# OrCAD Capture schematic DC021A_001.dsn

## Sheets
1 Page 3 - Hardware: size B; title: ADC1173EVM (Hardware); rev: A; note: DC021-001
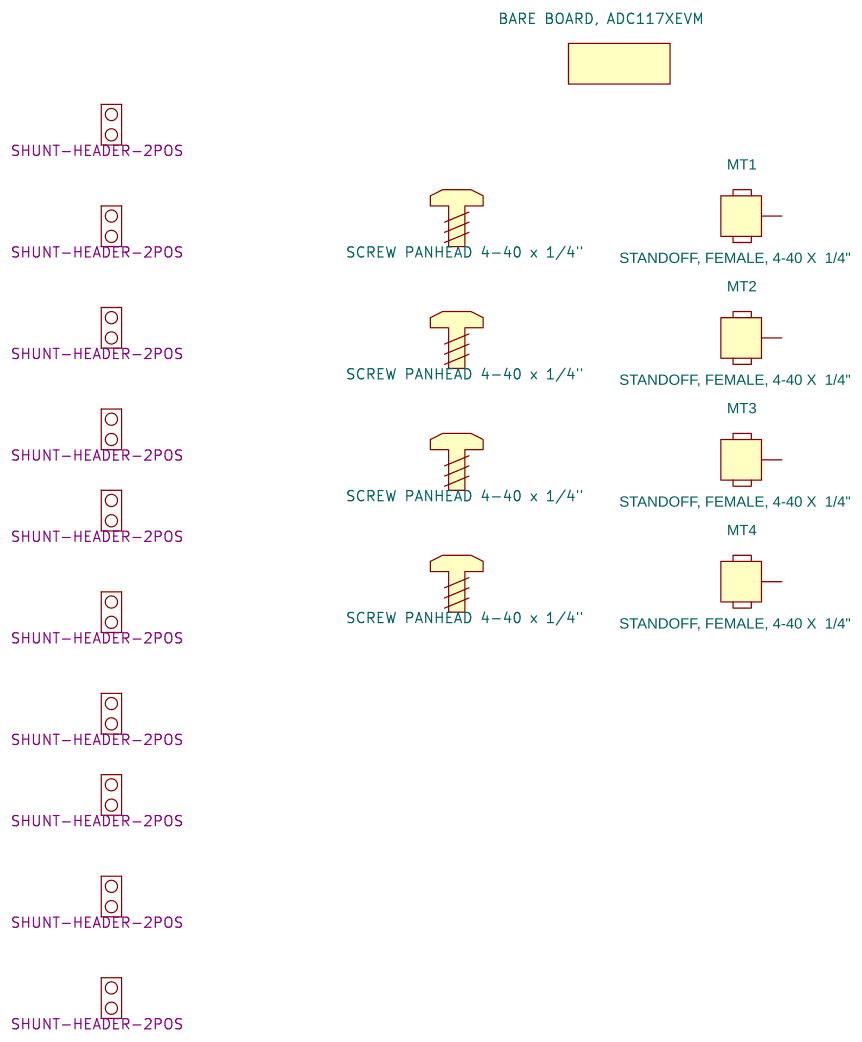
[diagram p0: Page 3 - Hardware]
2 Page 2 - Power: size B; title: ADC1173EVM (Power)
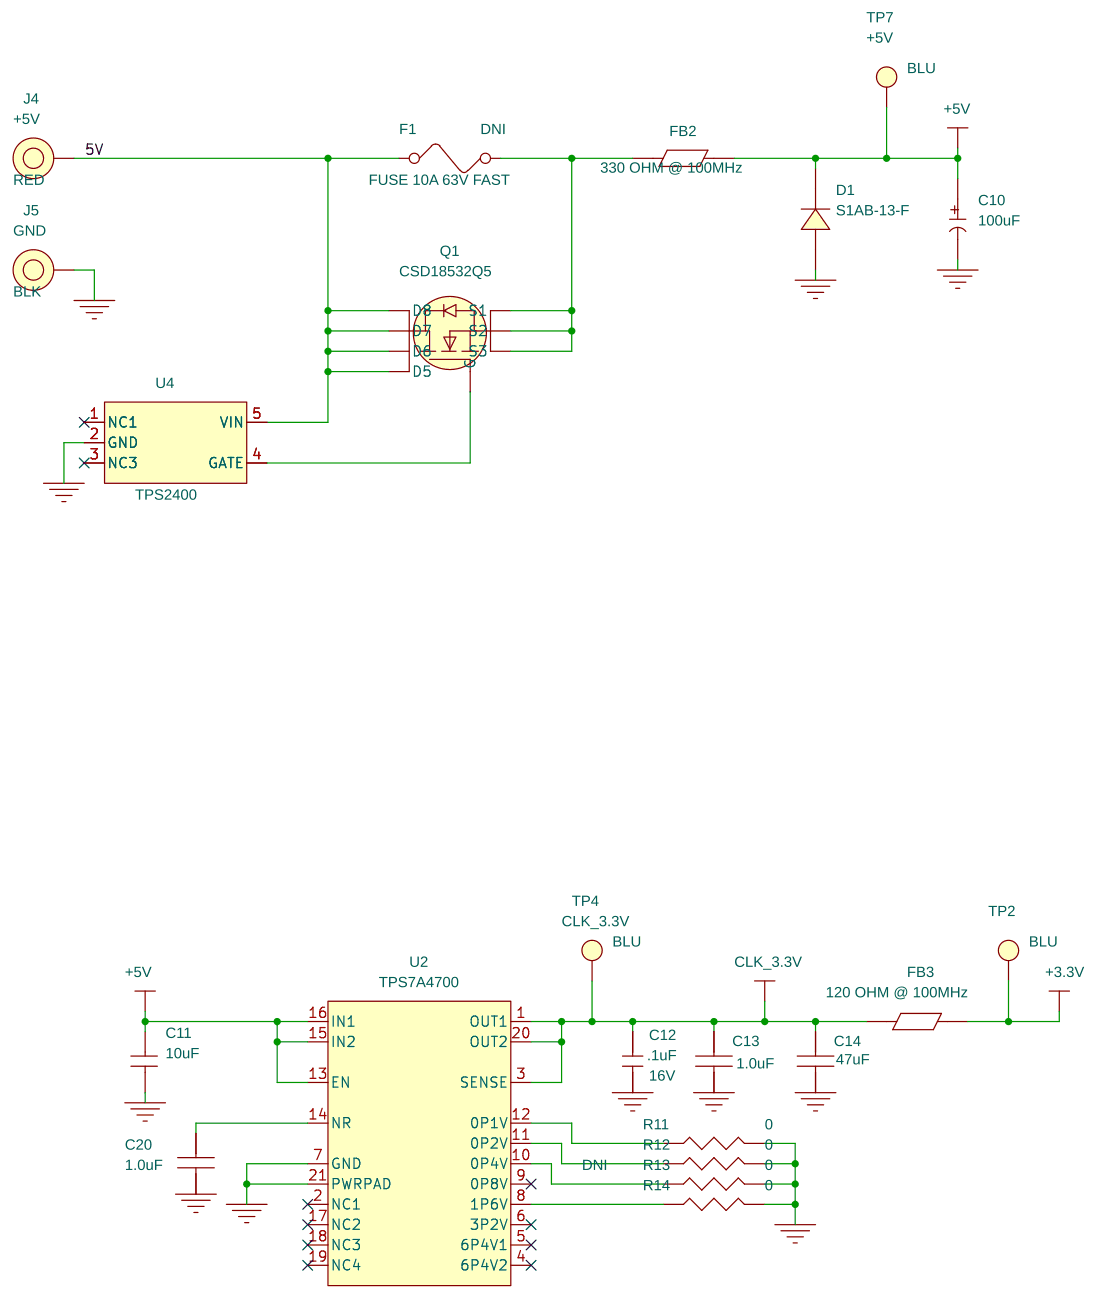
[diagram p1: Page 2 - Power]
3 Page 1 - Inputs: size B; title: ADC1173EVM
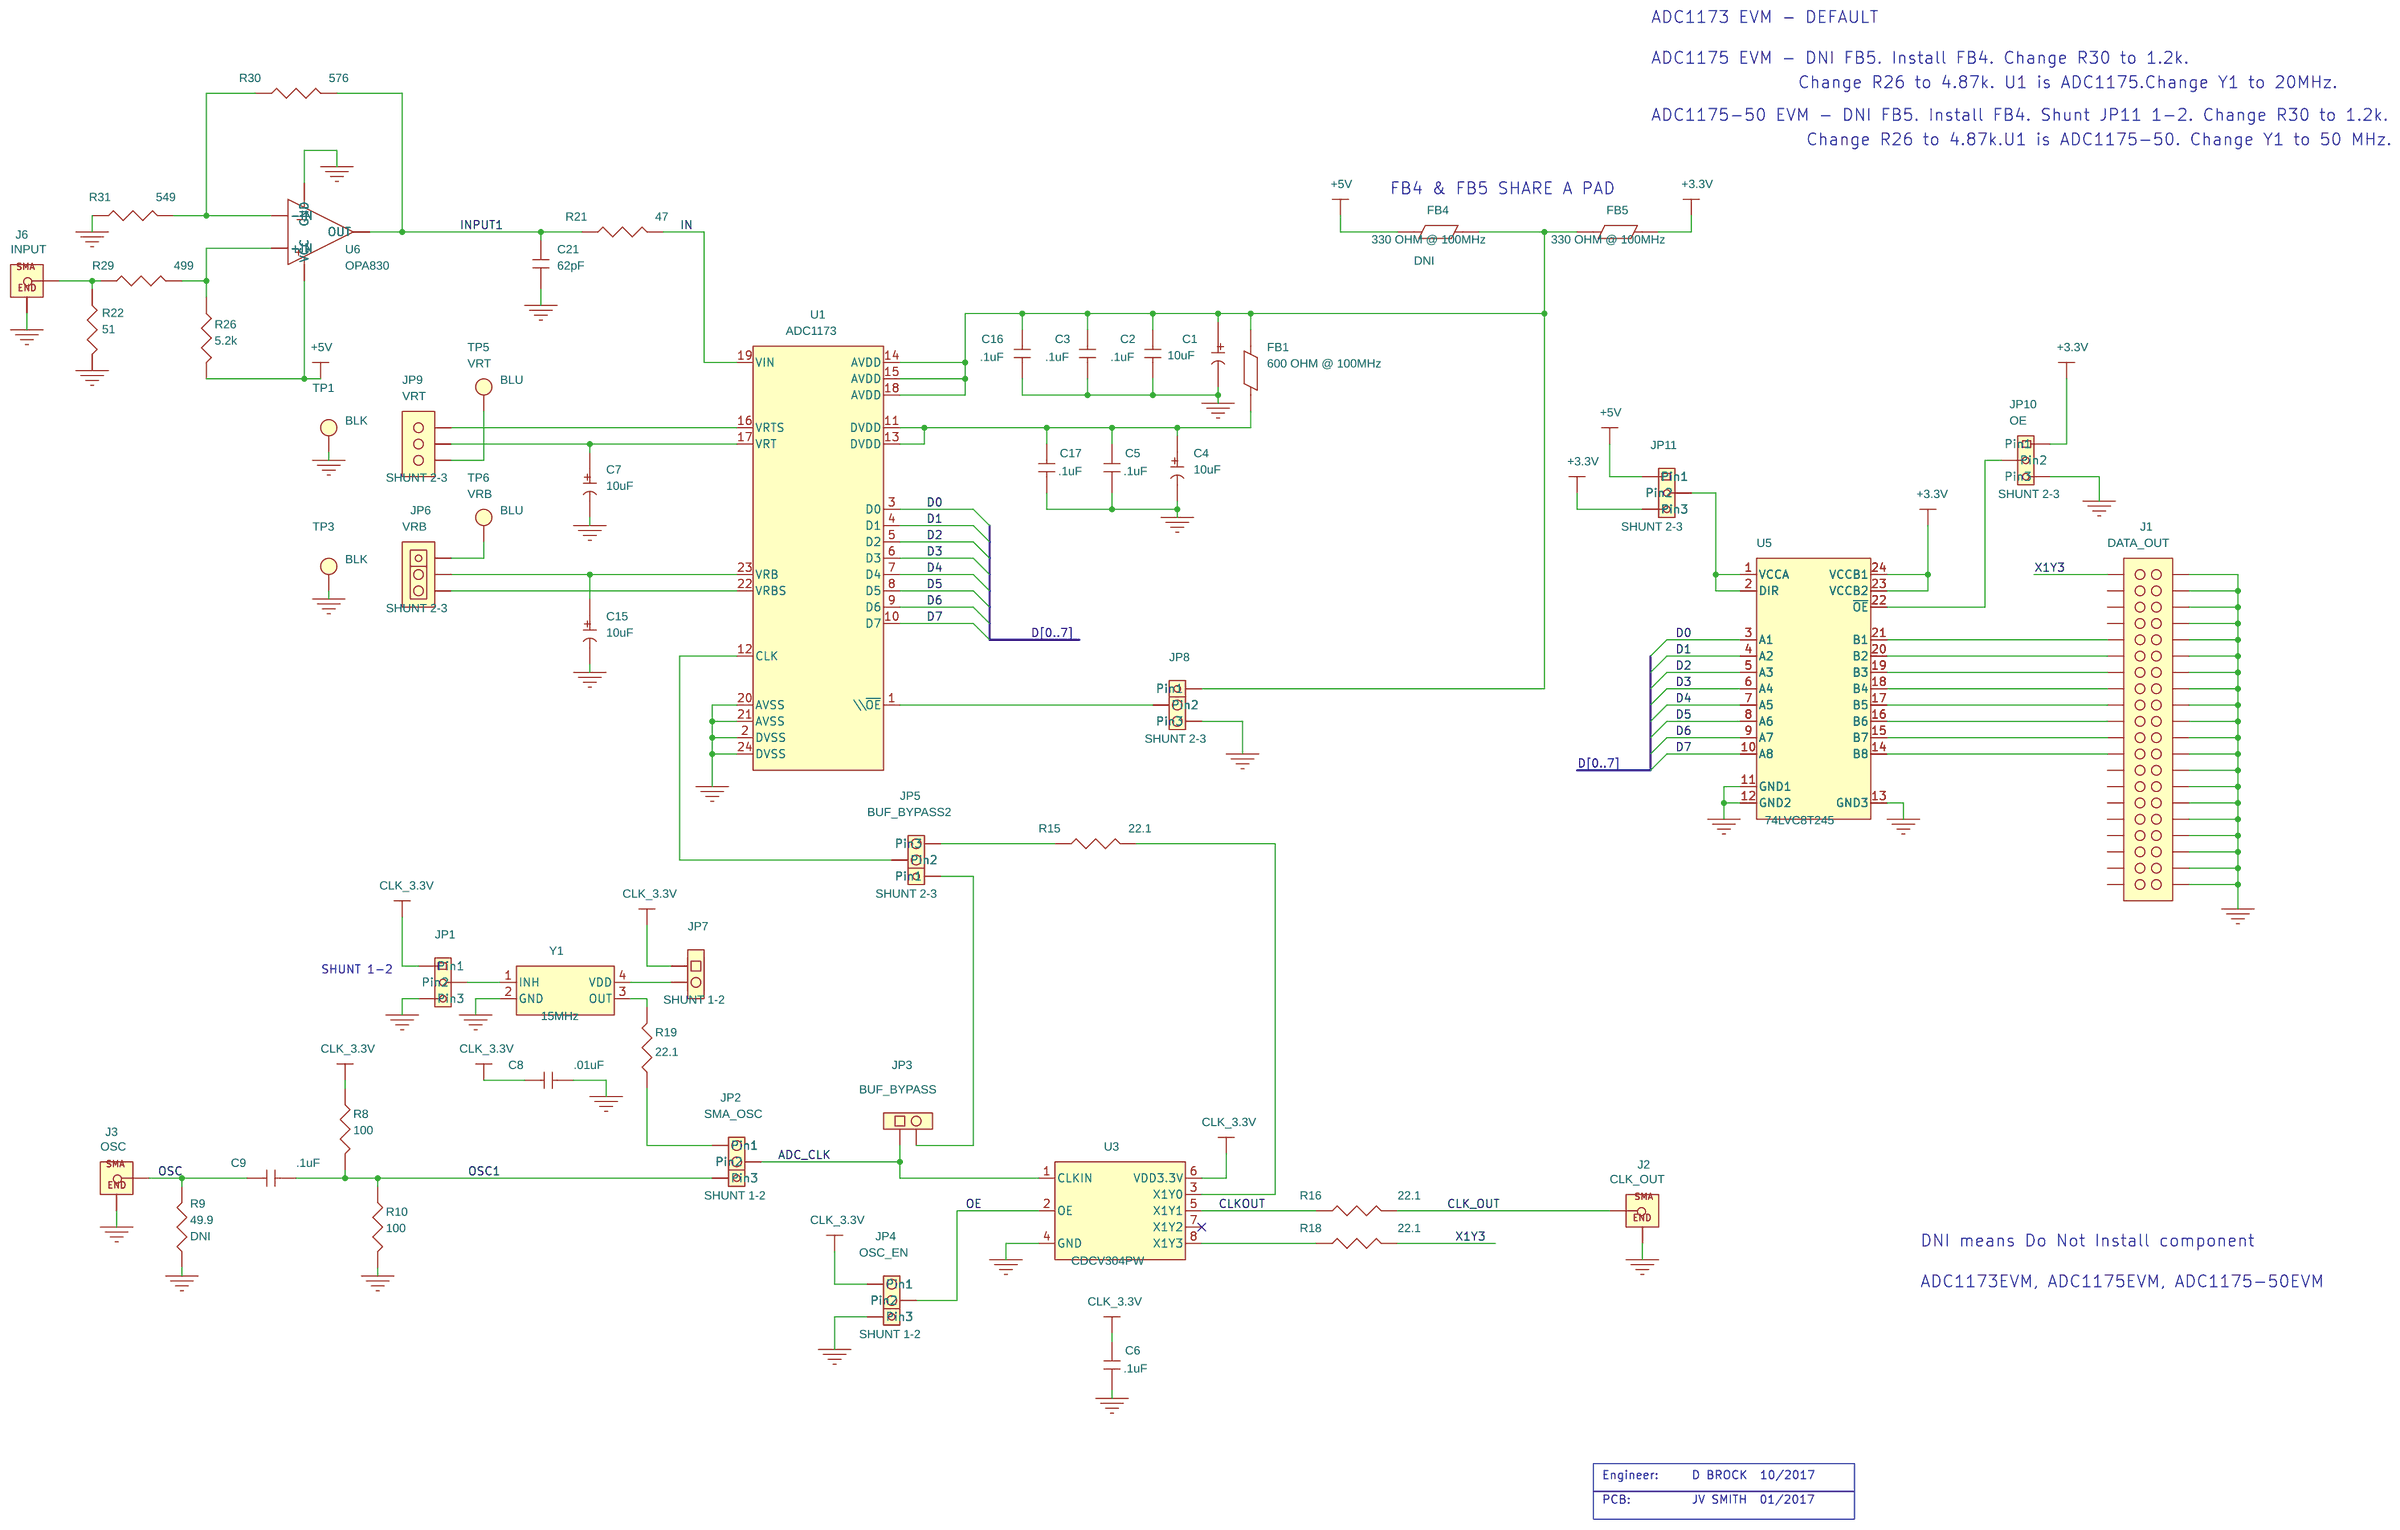
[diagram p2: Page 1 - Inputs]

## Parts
sheet Page 1 - Inputs
C1  10uF  [TANT_A]
C2  .1uF  [0402]
C3  .1uF  [0402]
C4  10uF  [TANT_A]
C5  .1uF  [0402]
C6  .1uF  [0402]
C7  10uF  [TANT_A]
C8  .01uF  [0402]
C9  .1uF  [0402]
C15  10uF  [TANT_A]
C16  .1uF  [0402]
C17  .1uF  [0402]
C21  62pF  [0402]
FB1  600 OHM @ 100MHz  [IND_0603]
FB4  330 OHM @ 100MHz  [IND_0603]
FB5  330 OHM @ 100MHz  [IND_0603]
J1  HDR, THVT, 40POS, .100  [HDR_THVT_2x20_100_M]
J2  SMA, THVT,  50OHMS  [SMA_THVT_312X312]
J3  SMA, THVT,  50OHMS  [SMA_THVT_312X312]
J6  SMA, THVT,  50OHMS  [SMA_THVT_312X312]
JP1  HEADER, 3POS, .100  [HDR_THVT_1x3_100_M]
JP2  HEADER, 3POS, .100  [HDR_THVT_1x3_100_M]
JP3  JUMPER_1X2_100  [HDR_THVT_1X2_100_M]
JP4  HEADER, 3POS, .100  [HDR_THVT_1x3_100_M]
JP5  HEADER, 3POS, .100  [HDR_THVT_1x3_100_M]
JP6  HEADER, 3POS, .100  [HDR_THVT_1x3_100_M]
JP7  HDR, 2POS, .100  [HDR_THVT_1X2_100_M]
JP8  HEADER, 3POS, .100  [HDR_THVT_1x3_100_M]
JP9  HEADER, 3POS, .100  [HDR_THVT_1x3_100_M]
JP10  JUMPER_1X3_100  [HDR_THVT_1x3_100_M]
JP11  HEADER, 3POS, .100  [HDR_THVT_1x3_100_M]
R8  100  [0402]
R9  49.9  [0402]
R10  100  [0402]
R15  22.1  [0402]
R16  22.1  [0402]
R18  22.1  [0402]
R19  22.1  [0402]
R21  47  [0402]
R22  51  [0402]
R26  5.2k  [0402]
R29  499  [0402]
R30  576  [0402]
R31  549  [0402]
TP1  BLK  [TP_THVT_100_RND_GND]
TP3  BLK  [TP_THVT_100_RND_GND]
TP5  BLU  [TP_THVT_100_RND]
TP6  BLU  [TP_THVT_100_RND]
U1  ADC1173  [TSSOP_24_311x177_26]
U3  CDCV304PW  [TSSOP_8_177x122_26]
U5  74LVC8T245  [SOIC_24_610x299_50]
U6  OPA830  [SOP_5_118x67_37]
Y1  15MHz  [XTAL_4_SM_85x104]
Z_SH-H1  SHUNT-HEADER
Z_SH-H2  SHUNT-HEADER
Z_SH-H4  SHUNT-HEADER
Z_SH-H5  SHUNT-HEADER
Z_SH-H6  SHUNT-HEADER
Z_SH-H7  SHUNT-HEADER
Z_SH-H8  SHUNT-HEADER
Z_SH-J1  SHUNT-HEADER
sheet Page 2 - Power
C10  100uF  [TANT_D]
C11  10uF  [0805]
C12  .1uF  [0402]
C13  1.0uF  [0603]
C14  47uF  [1206]
C20  1.0uF  [0603]
D1  S1AB-13-F  [DIODE_S1AB_SMB]
F1  FUSE 10A 63V FAST  [1206]
FB2  330 OHM @ 100MHz  [IND_0603]
FB3  120 OHM @ 100MHz  [1206]
J4  RED  [JACK_THVT_BANANA_315DRILL]
J5  BLK  [JACK_THVT_BANANA_315DRILL]
Q1  CSD18532Q5  [SON_Q5B_8]
R11  0  [0402]
R12  0  [0402]
R13  0  [0402]
R14  0  [0402]
TP2  BLU  [TP_THVT_100_RND]
TP4  BLU  [TP_THVT_100_RND]
TP7  BLU  [TP_THVT_100_RND]
U2  TPS7A4700  [qfn20_rgw_p65pitch]
U4  TPS2400  [DBV5]
sheet Page 3 - Hardware
MT1  STANDOFF, FEMALE, 4-40 X  1/4"  [MFG125_PLATED]
MT2  STANDOFF, FEMALE, 4-40 X  1/4"  [MFG125_PLATED]
MT3  STANDOFF, FEMALE, 4-40 X  1/4"  [MFG125_PLATED]
MT4  STANDOFF, FEMALE, 4-40 X  1/4"  [MFG125_PLATED]
Z_BOARD2  BARE BOARD, ADC117XEVM
Z_SCREW2  SCREW PANHEAD 4-40 x 1/4"
Z_SCREW3  SCREW PANHEAD 4-40 x 1/4"
Z_SCREW4  SCREW PANHEAD 4-40 x 1/4"
Z_SCREW5  SCREW PANHEAD 4-40 x 1/4"
Z_SH-J2  SHUNT- HEADER
Z_SH-J3  SHUNT- HEADER
Z_SH-J4  SHUNT- HEADER
Z_SH-J5  SHUNT- HEADER
Z_SH-J6  SHUNT- HEADER
Z_SH-J7  SHUNT- HEADER
Z_SH-J8  SHUNT- HEADER
Z_SH-J9  SHUNT- HEADER
Z_SH-J10  SHUNT- HEADER
Z_SH-J11  SHUNT- HEADER

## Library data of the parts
C1 C4 C7 C15 = CAP_TANT_A_0: Mfr_Part_Number: T491A106K010AT
C2 C3 C5 C6 C9 C16 C17 = CAP_0402_0.1uF
C8 = CAP_0402_0.01uF
C21 = CAP_0402_68pF: Mfr_Name: SAMSUNG; Mfr_Part_Number: CL05C620JB5NNNC
FB1 = FERRITE_BEAD_0603_600_H: Mfr_Part_Number: BLM18AG601SN1D
FB4 = FERRITE_BEAD_0603_600_H: Mfr_Part_Number: BLM18PG331SN1D_DNI; Note: DNI
FB5 = FERRITE_BEAD_0603_600_H: Mfr_Part_Number: BLM18PG331SN1D
J1 = HEADER_2x20_100: Mfr_Part_Number: TSW-120-07-G-D; TI_SILKTEXT: DATA_OUT
J2 = TMP_102603: Mfr_Part_Number: 142-0701-201; TI_Silktext: CLK_OUT
J3 = TMP_102603: Mfr_Part_Number: 142-0701-201; TI_Silktext: OSC
J6 = TMP_102603: Mfr_Part_Number: 142-0701-201; TI_Silktext: INPUT
JP1 = JUMPER_1X3_100
JP2 = JUMPER_1X3_100: Note: SHUNT 1-2; TI_Silktext: SMA_OSC
JP3 = JUMPER_1X2_100: SILK: BUF_BYPASS
JP4 = JUMPER_1X3_100: Note: SHUNT 1-2; TI_Silktext: OSC_EN
JP5 = JUMPER_1X3_100: Note: SHUNT 2-3; TI_Silktext: BUF_BYPASS2
JP6 = HEADER_1x3_100: Note: SHUNT 2-3; TI_SILKTEXT: VRB
JP7 = JUMPER_1X2_100: Note: SHUNT 1-2; SILK: SILK
JP8 JP11 = JUMPER_1X3_100: Note: SHUNT 2-3; TI_Silktext: ADC_OE
JP9 = HEADER_1x3_100: Note: SHUNT 2-3; TI_SILKTEXT: VRT
JP10 = JUMPER_1X3_100: Note: SHUNT 2-3; TI_Silktext: OE
R8 R10 = Res_0402_100
R9 = Res_0402_49.9_H: Mfr_Part_Number: ERJ-2RKF49R9X_DNI; Note: DNI
R15 R16 R18 R19 = Res_0402_22.1_H
R21 = Res_0402_47
R22 = Res_0402_51_.5%: Mfr_Part_Number: ERA-2AED510X; TOL: .1%
R26 = Res_0805_21.5k: Mfr_Part_Number: ERJ-2RKF5231X
R29 = Res_0402_499_H
R30 = Res_0402_1.2k: Mfr_Part_Number: ERJ-2RKF5760X
R31 = Res_0402_560_H: Mfr_Part_Number: ERJ-2RKF5490X
TP1 TP3 = TESTPOINT_BLK
TP5 = TESTPOINT_BLUE: TI_SILKTEXT: VRT
TP6 = TESTPOINT_BLUE: TI_SILKTEXT: VRB
U1 = ADC1175: Mfr_Part_Number: ADC1173CIMTCX/NOPB
U3 = CDCV304PW
U5 = SN74LVC8T245
U6 = OPA376DCK: Mfr_Part_Number: OPA830IDBVT
Y1 = OSC_4_SM_KYOCERA_40MHz: Mfr_Name: EPSON; Mfr_Part_Number: SG-210STF 15.000000MHz
Z_SH-H1 Z_SH-H2 Z_SH-H4-Z_SH-H8 = SHUNT-HEADER_-_3POS
Z_SH-J1 = SHUNT-HEADER_-_2POS
C10 = CAP_TANT_D_0: Mfr_Name: Panasonic; Mfr_Part_Number: 20TQC100MYF
C11 = CAP_NP_1: Mfr_Name: MURATA; Mfr_Part_Number: GRM21BR61E106KA73L; TOL: 10%; VOLTAGE: 25V
C12 = CAP0603: Mfr_Name: MURATA; Mfr_Part_Number: GRM155R71C104KA88D; TOL: 10%; Voltage: 16V
C13 C20 = CAP_NP_0: Mfr_Name: TDK CORP; Mfr_Part_Number: C1608X7R1C105K080AC; TOL: 10%; VOLTAGE: 16V
C14 = CAP_NP_0: Mfr_Name: MURATA; Mfr_Part_Number: GRM31CR61A476ME15L; TOL: 20%; VOLTAGE: 10V
D1 = DIODE_S1BB
F1 = FUSE_0: Mfr_Name: TE Connectivity; Mfr_Part_Number: 1206SFF200F/63-2_DNI; Note: DNI
FB2 = FERRITE_BEAD_0603_600_H: Mfr_Part_Number: LM18PG331SN1D
FB3 = FERRITE_BEAD_1206_120_H: Mfr_Part_Number: BLM31PG121SN1L
J4 = BANANA_JACK_RED_RoHS: Mfr_Name: TENMA; Mfr_Part_Number: SPC15363; TI_Silktext: +5V
J5 = BANANA_JACK_BLK_RoHS: Mfr_Name: TENMA; Mfr_Part_Number: SPC15354; TI_Silktext: GND
Q1 = CSD18532Q5B: Mfr_Name: Texas Instruments
R11-R13 = R: Mfr_Name: PANASONIC; Mfr_Part_Number: ERJ-2GE0R00X_DNI; Note: DNI; TOL: 5%
R14 = R: Mfr_Name: PANASONIC; Mfr_Part_Number: ERJ-2GE0R00X; TOL: 5%
TP2 = TESTPOINT_BLUE: TI_SILKTEXT: +3V
TP4 = TESTPOINT_BLUE: TI_SILKTEXT: CLK_3.3V
TP7 = TESTPOINT_BLUE: TI_SILKTEXT: +5V
U2 = TPS7A4700: Mfr_Name: Texas Instruments; Mfr_Part_Number: TPS7A4700RGWT
U4 = TPS2400: Mfr_Name: Texas Instruments; Mfr_Part_Number: TPS2400DBVT
MT1-MT4 = MOUNTING_HOLE_1_3_16: Mfr_Name: KEYSTONE; Mfr_Part_Number: 1891
Z_BOARD2 = BARE_BOARD: Mfr_Name: TTM; Mfr_Part_Number: ADC1173EVM REV A
Z_SCREW2-Z_SCREW5 = STANDOFF-SCREW_3_4: Mfr_Part_Number: PMSSS 440 0025 PH
Z_SH-J2-Z_SH-J11 = SHUNT-HEADER_-_2POS: ID: SHUNT-HEADER-2POS; Note: SHUNT-HEADER-2POS

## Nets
5V: F1.1 J4.1 Q1.5(D5) Q1.6(D6) Q1.7(D7) Q1.8(D8) U4.5(VIN)
+3.3V: FB3.2 FB5.2 JP10.1(Pin1) JP11.3(Pin3) TP2.1(TP) U5.23(VCCB2) U5.24(VCCB1)
+5V: C10.1 C11.1 D1.2(CATHODE) FB2.2 FB4.1 JP11.1(Pin1) R26.2 TP7.1(TP) U2.13(EN) U2.15(IN2) U2.16(IN1) U6.5(VCC)
GND: C1.2 C2.2 C3.2 C4.2 C5.2 C6.2 C7.2 C8.2 C10.2 C11.2 C12.2 C13.2 C14.2 C15.2 C16.2 C17.2 C20.2 C21.2 D1.1(ANODE) J1.2 J1.4 J1.6 J1.8 J1.10 J1.12 J1.14 J1.16 J1.18 J1.20 J1.22 J1.24 J1.26 J1.28 J1.30 J1.32 J1.34 J1.36 J1.38 J1.40 J2.2(GND) J2.3(GND) J2.4(GND) J2.5(GND) J3.2(GND) J3.3(GND) J3.4(GND) J3.5(GND) J5.1 J6.2(GND) J6.3(GND) J6.4(GND) J6.5(GND) JP1.3(Pin3) JP4.3(Pin3) JP8.3(Pin3) JP10.3(Pin3) R9.1 R10.2 R11.1 R12.1 R13.1 R14.1 R22.2 R31.1 TP1.1(TP) TP3.1(TP) U1.2(DVSS) U1.20(AVSS) U1.21(AVSS) U1.24(DVSS) U2.7(GND) U2.21(PWRPAD) U3.4(GND) U4.2(GND) U5.11(GND1) U5.12(GND2) U5.13(GND3) U6.2(GND) Y1.2(GND)
ADC_CLK: JP2.2(Pin2) JP3.1 U3.1(CLKIN)
CLK_3.3V: C6.1 C8.1 C12.1 C13.1 C14.1 FB3.1 JP1.1(Pin1) JP4.1(Pin1) JP7.1 R8.1 TP4.1(TP) U2.1(OUT1) U2.3(SENSE) U2.20(OUT2) U3.6(VDD3.3V)
CLK_OUT: J2.1(CENTER) R16.2
CLKOUT: R16.1 U3.5(X1Y1)
D0: U1.3(D0) U5.3(A1)
D1: U1.4(D1) U5.4(A2)
D2: U1.5(D2) U5.5(A3)
D3: U1.6(D3) U5.6(A4)
D4: U1.7(D4) U5.7(A5)
D5: U1.8(D5) U5.8(A6)
D6: U1.9(D6) U5.9(A7)
D7: U1.10(D7) U5.10(A8)
IN: R21.1 U1.19(VIN)
INPUT1: C21.1 R21.2 R30.2 U6.4(OUT)
OE: JP4.2(Pin2) U3.2(OE)
OSC: C9.1 J3.1(CENTER) R9.2
OSC1: C9.2 JP2.3(Pin3) R8.2 R10.1
X1Y3: J1.1 R18.2
N19769118: R19.2 Y1.3(OUT)
N19769226: JP2.1(Pin1) R19.1
N19799665: R15.2 U3.3(X1Y0)
N19799687: R18.1 U3.8(X1Y3)
N19818955: J1.23 U5.14(B8)
N19818957: J1.21 U5.15(B7)
N19818959: J1.19 U5.16(B6)
N19818961: J1.17 U5.17(B5)
N19819026: J1.9 U5.21(B1)
N19819028: J1.11 U5.20(B2)
N19819030: J1.13 U5.19(B3)
N19819032: J1.15 U5.18(B4)
N19819185: JP3.2 JP5.1(Pin1)
N19819194: JP5.2(Pin2) U1.12(CLK)
N19819218: JP5.3(Pin3) R15.1
N19821064: JP1.2(Pin2) Y1.1(INH)
N19821339: JP7.2 Y1.4(VDD)
N19861116: C1.1 C2.1 C3.1 C16.1 FB1.2 FB4.2 FB5.1 JP8.1(Pin1) U1.14(AVDD) U1.15(AVDD) U1.18(AVDD)
N19861142: C4.1 C5.1 C17.1 FB1.1 U1.11(DVDD) U1.13(DVDD)
N19864072: J6.1(CENTER) R22.1 R29.1
N19864545: JP8.2(Pin2) U1.1(\\~{OE})
N19865533: JP9.3 U1.16(VRTS)
N19865546: C7.1 JP9.2 U1.17(VRT)
N19865555: JP9.1 TP5.1(TP)
N19865562: C15.1 JP6.2 U1.23(VRB)
N19865571: JP6.3 U1.22(VRBS)
N19865580: JP6.1 TP6.1(TP)
N19873407: C20.1 U2.14(NR)
N19873435: R14.2 U2.8(1P6V)
N19873437: R12.2 U2.11(0P2V)
N19873439: R11.2 U2.12(0P1V)
N19873449: R13.2 U2.10(0P4V)
N19874252: F1.2 FB2.1 Q1.1(S1) Q1.2(S2) Q1.3(S3)
N19874302: Q1.4(G) U4.4(GATE)
N19886844: JP10.2(Pin2) U5.22(~{OE})
N19887644: JP11.2(Pin2) U5.1(VCCA) U5.2(DIR)
N19892118: R26.1 R29.2 U6.1(+IN)
N19894018: R30.1 R31.2 U6.3(-IN)

Not connected (* = marked no-connect by the designer): J1 3 5 7 25 27 29 31 33 35 37 39; MT1 1; MT2 1; MT3 1; MT4 1; U2 2(NC1)* 4(6P4V2)* 5(6P4V1)* 6(3P2V)* 9(0P8V)* 17(NC2)* 18(NC3)* 19(NC4)*; U3 7(X1Y2)*; U4 1(NC1)* 3(NC3)*

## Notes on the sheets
sheet 3
- ADC1173 EVM - DEFAULT
- ADC1175 EVM - DNI FB5. Install FB4. Change R30 to 1.2k.
- Change R26 to 4.87k. U1 is ADC1175.Change Y1 to 20MHz.
- ADC1175-50 EVM - DNI FB5. Install FB4. Shunt JP11 1-2. Change R30 to 1.2k.
- Change R26 to 4.87k.U1 is ADC1175-50. Change Y1 to 50 MHz.
- FB4 & FB5 SHARE A PAD
- SHUNT 1-2
- DNI means Do Not Install component
- ADC1173EVM, ADC1175EVM, ADC1175-50EVM
- Engineer:
- D BROCK  10/2017
- PCB:
- JV SMITH  01/2017
